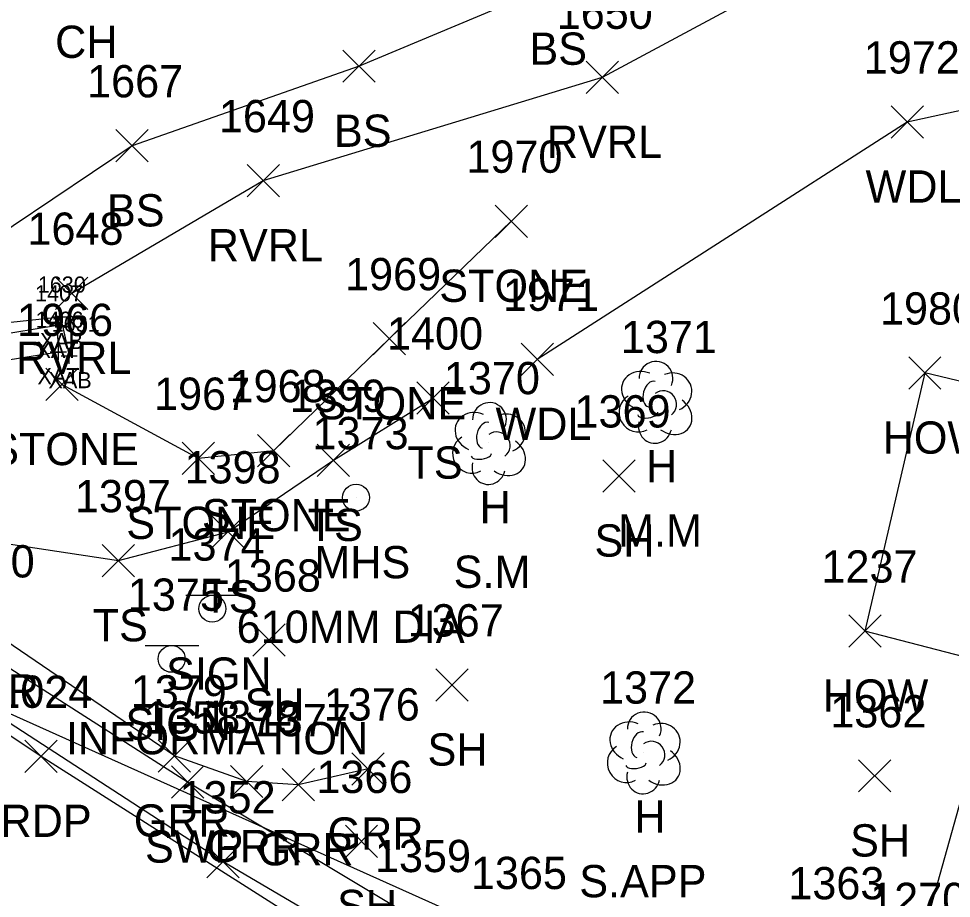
# Model space of a CAD drawing. Extents: x 1616726 to 1619875, y 273782 to 276557.
# Drawn here: x 1617087.2 to 1617145, y 276211.4 to 276265.9 of the extents above; entities that cross this region are included whole.
import ezdxf

# ---------------------------------------------------------------- set-up
doc = ezdxf.new("R2010")
doc.units = 0
for name, color, linetype in [('B_A', 7, 'Continuous'), ('B_I', 7, 'Continuous'), ('B_TIC', 7, 'Continuous'), ('BSUBM', 7, 'Continuous'), ('DCP', 7, 'Continuous'), ('L_A', 7, 'Continuous'), ('L_C', 7, 'Continuous'), ('L_I', 7, 'Continuous'), ('L_TIC', 7, 'Continuous'), ('LASF', 7, 'Continuous'), ('LAWA', 7, 'Continuous'), ('LAWE', 7, 'Continuous'), ('LBC', 7, 'Continuous'), ('LELB', 7, 'Continuous'), ('LTD', 7, 'Continuous'), ('P_A', 7, 'Continuous'), ('P_I', 7, 'Continuous'), ('P_TIC', 7, 'Continuous'), ('PET', 7, 'Continuous'), ('R_A', 7, 'Continuous'), ('R_I', 7, 'Continuous'), ('R_TIC', 7, 'Continuous'), ('RDP', 7, 'Continuous'), ('RGR', 7, 'Continuous'), ('RSW', 7, 'Continuous'), ('S_A', 7, 'Continuous'), ('S_C', 7, 'Continuous'), ('S_I', 7, 'Continuous'), ('SSGN', 7, 'Continuous'), ('U_A', 7, 'Continuous'), ('U_C', 7, 'Continuous'), ('U_I', 7, 'Continuous'), ('USMH', 7, 'Continuous')]:
    doc.layers.add(name, color=color, linetype=linetype)

msp = doc.modelspace()

# ---------------------------------------------------------------- linework, layer by layer
at = {"layer": 'B_TIC'}
for p, q in [((1617089.817, 276247.416), (1617089.893, 276247.416)), ((1617089.624, 276246.874), (1617089.699, 276246.874)), ((1617089.68, 276245.238), (1617089.755, 276245.238)), ((1617090.348, 276244.994), (1617090.423, 276244.994))]:
    msp.add_line(p, q, dxfattribs=at)
for points in [[(1617089.814, 276246.916), (1617089.814, 276247.916)], [(1617089.314, 276247.416), (1617090.314, 276247.416)], [(1617089.62, 276246.374), (1617089.62, 276247.374)], [(1617089.12, 276246.874), (1617090.12, 276246.874)], [(1617089.176, 276245.238), (1617090.176, 276245.238)], [(1617089.676, 276244.738), (1617089.676, 276245.738)], [(1617090.344, 276244.494), (1617090.344, 276245.494)], [(1617089.844, 276244.994), (1617090.844, 276244.994)]]:
    msp.add_lwpolyline(points, dxfattribs=at)
at = {"layer": 'BSUBM'}
for points in [[(1617010.577, 276214.426), (1617009.604, 276215.712), (1617012.165, 276218.528), (1617020.162, 276225.998), (1617024.806, 276230.09), (1617027.157, 276232.146), (1617038.443, 276235.694), (1617050.909, 276239.585), (1617068.456, 276245.114), (1617089.814, 276247.416), (1617090.344, 276244.994)], [(1617069.472, 276243.57), (1617067.092, 276242.73), (1617068.432, 276241.721), (1617069.867, 276242.108), (1617089.676, 276245.238), (1617089.62, 276246.874)], [(1617089.62, 276246.874), (1617069.472, 276243.57)]]:
    msp.add_lwpolyline(points, dxfattribs=at)
at = {"layer": 'DCP'}
msp.add_lwpolyline([(1617248.526, 276150.098), (1617074.525, 276228.268)], dxfattribs=at)
at = {"layer": 'L_TIC'}
for points in [[(1617107.303, 276261.949), (1617109.303, 276263.949)], [(1617109.303, 276261.949), (1617107.303, 276263.949)], [(1617122.367, 276261.261), (1617124.367, 276263.261)], [(1617124.367, 276261.261), (1617122.367, 276263.261)], [(1617141.251, 276258.493), (1617143.251, 276260.493)], [(1617143.251, 276258.493), (1617141.251, 276260.493)], [(1617093.244, 276257.017), (1617095.244, 276259.017)], [(1617095.244, 276257.017), (1617093.244, 276259.017)], [(1617101.367, 276254.855), (1617103.367, 276256.855)], [(1617103.367, 276254.855), (1617101.367, 276256.855)], [(1617116.725, 276252.342), (1617118.725, 276254.342)], [(1617118.725, 276252.342), (1617116.725, 276254.342)], [(1617089.502, 276247.878), (1617091.502, 276249.878)], [(1617091.502, 276247.878), (1617089.502, 276249.878)], [(1617109.18, 276245.064), (1617111.18, 276247.064)], [(1617111.18, 276245.064), (1617109.18, 276247.064)], [(1617118.334, 276243.786), (1617120.334, 276245.786)], [(1617120.334, 276243.786), (1617118.334, 276245.786)], [(1617142.341, 276242.936), (1617144.341, 276244.936)], [(1617144.341, 276242.936), (1617142.341, 276244.936)], [(1617088.91, 276242.226), (1617090.91, 276244.226)], [(1617090.91, 276242.226), (1617088.91, 276244.226)], [(1617111.886, 276241.385), (1617113.886, 276243.385)], [(1617113.886, 276241.385), (1617111.886, 276243.385)], [(1617102.02, 276238.126), (1617104.02, 276240.126)], [(1617104.02, 276238.126), (1617102.02, 276240.126)], [(1617097.342, 276237.652), (1617099.342, 276239.652)], [(1617099.342, 276237.652), (1617097.342, 276239.652)], [(1617105.708, 276237.525), (1617107.708, 276239.525)], [(1617107.708, 276237.525), (1617105.708, 276239.525)], [(1617123.392, 276236.558), (1617125.392, 276238.558)], [(1617125.392, 276236.558), (1617123.392, 276238.558)], [(1617099.185, 276233.092), (1617101.185, 276235.092)], [(1617101.185, 276233.092), (1617099.185, 276235.092)], [(1617092.393, 276231.307), (1617094.393, 276233.307)], [(1617094.393, 276231.307), (1617092.393, 276233.307)], [(1617138.631, 276226.947), (1617140.631, 276228.947)], [(1617140.631, 276226.947), (1617138.631, 276228.947)], [(1617101.724, 276226.387), (1617103.724, 276228.387)], [(1617103.724, 276226.387), (1617101.724, 276228.387)], [(1617113.051, 276223.607), (1617115.051, 276225.607)], [(1617115.051, 276223.607), (1617113.051, 276225.607)], [(1617139.224, 276217.972), (1617141.224, 276219.972)], [(1617141.224, 276217.972), (1617139.224, 276219.972)], [(1617107.452, 276213.908), (1617109.452, 276215.908)], [(1617109.452, 276213.908), (1617107.452, 276215.908)]]:
    msp.add_lwpolyline(points, dxfattribs=at)
at = {"layer": 'LASF'}
msp.add_lwpolyline([(1617089.91, 276243.226), (1617098.342, 276238.652), (1617103.02, 276239.126), (1617110.18, 276246.064), (1617117.725, 276253.342)], dxfattribs=at)
at = {"layer": 'LAWA'}
msp.add_lwpolyline([(1617119.334, 276244.786), (1617142.251, 276259.493), (1617164.142, 276264.272), (1617183.103, 276270.097), (1617194.136, 276272.184)], dxfattribs=at)
at = {"layer": 'LAWE'}
msp.add_lwpolyline([(1617090.502, 276248.878), (1617102.367, 276255.855), (1617123.367, 276262.261), (1617141.244, 276271.864), (1617161.153, 276280.417), (1617181.534, 276284.745)], dxfattribs=at)
at = {"layer": 'LBC'}
for points in [[(1617202.986, 276236.707), (1617169.05, 276244.707), (1617152.443, 276247.898), (1617150.919, 276242.13), (1617143.341, 276243.936)], [(1617143.341, 276243.936), (1617139.631, 276227.947)], [(1617255.861, 276201.85), (1617245.993, 276203.869), (1617245.387, 276204.035), (1617236.024, 276205.957), (1617235.421, 276203.64), (1617213.935, 276208.22), (1617213.334, 276206.295), (1617177.812, 276214.354), (1617179.361, 276218.267), (1617161.118, 276222.362), (1617159.601, 276222.749), (1617139.631, 276227.947)]]:
    msp.add_lwpolyline(points, dxfattribs=at)
at = {"layer": 'LELB'}
for points in [[(1617180.325, 276288.326), (1617161.431, 276281.848), (1617137.104, 276278.445), (1617120.409, 276268.034), (1617108.303, 276262.949), (1617094.244, 276258.017), (1617079.483, 276248.101), (1617068.225, 276247.781), (1617049.151, 276245.503), (1617035.056, 276240.813), (1617026.009, 276236.235), (1617014.974, 276241.9), (1616972.474, 276247.818), (1616960.605, 276245.765), (1616944.032, 276250.468), (1616920.652, 276257.271), (1616898.689, 276263.021), (1616845.503, 276278.094), (1616816.834, 276290.556), (1616792.378, 276296.226)], [(1617074.01, 276240.881), (1617083.704, 276233.783), (1617093.393, 276232.307), (1617100.185, 276234.092), (1617106.708, 276238.525), (1617112.886, 276242.385)]]:
    msp.add_lwpolyline(points, dxfattribs=at)
at = {"layer": 'LTD'}
for p, q in [((1617126.64, 276242.168), (1617126.64, 276242.168)), ((1617126.64, 276242.168), (1617126.64, 276242.168)), ((1617116.332, 276239.62), (1617116.332, 276239.62)), ((1617116.332, 276239.62), (1617116.332, 276239.62)), ((1617125.915, 276220.448), (1617125.915, 276220.448)), ((1617125.915, 276220.448), (1617125.915, 276220.448))]:
    msp.add_line(p, q, dxfattribs=at)
for centre in [(1617126.687, 276243.602), (1617116.379, 276241.054), (1617125.962, 276221.882)]:
    msp.add_arc(centre, 1.047, 335.52715, 180.95627, dxfattribs=at)
for centre, major_axis, ratio, start_param, end_param in [((1617125.848, 276242.835), (1.21, -0.512), 0.895232, 1.570796, 4.712389), ((1617127.681, 276242.752), (-1.141, -0.483), 0.949671, 1.570796, 4.712389), ((1617126.431, 276242.626), (-0.208, -0.792), 0.645439, 3.141593, 6.283185), ((1617127.14, 276242.002), (-0.5, 0.667), 0.989748, 3.141593, 6.283185), ((1617125.557, 276241.46), (0.584, -1.042), 0.959034, 3.141593, 6.283185), ((1617127.64, 276241.335), (-1.09, 0.792), 0.841452, 1.570796, 4.712389), ((1617115.54, 276240.287), (1.21, -0.512), 0.895232, 1.570796, 4.712389), ((1617117.374, 276240.203), (-1.141, -0.483), 0.949671, 1.570796, 4.712389), ((1617126.182, 276241.418), (-0.625, -0.083), 0.423636, 0, 3.141593), ((1617116.124, 276240.078), (-0.208, -0.792), 0.645439, 3.141593, 6.283185), ((1617126.64, 276240.668), (0.265, 1.061), 0.942809, 1.570796, 4.712389), ((1617116.832, 276239.453), (-0.5, 0.667), 0.989748, 3.141593, 6.283185), ((1617115.249, 276238.911), (0.584, -1.042), 0.959034, 3.141593, 6.283185), ((1617117.332, 276238.787), (-1.09, 0.792), 0.841452, 1.570796, 4.712389), ((1617115.874, 276238.87), (-0.625, -0.083), 0.423636, 0, 3.141593), ((1617116.332, 276238.12), (0.265, 1.061), 0.942809, 1.570796, 4.712389), ((1617125.124, 276221.114), (1.21, -0.512), 0.895232, 1.570796, 4.712389), ((1617126.957, 276221.031), (-1.141, -0.483), 0.949671, 1.570796, 4.712389), ((1617125.707, 276220.906), (-0.208, -0.792), 0.645439, 3.141593, 6.283185), ((1617126.415, 276220.281), (-0.5, 0.667), 0.989748, 3.141593, 6.283185), ((1617124.832, 276219.739), (0.584, -1.042), 0.959034, 3.141593, 6.283185), ((1617126.916, 276219.615), (-1.09, 0.792), 0.841452, 1.570796, 4.712389), ((1617125.457, 276219.698), (-0.625, -0.083), 0.423636, 0, 3.141593), ((1617125.916, 276218.948), (0.265, 1.061), 0.942809, 1.570796, 4.712389)]:
    msp.add_ellipse(centre, major_axis=major_axis, ratio=ratio, start_param=start_param, end_param=end_param, dxfattribs=at)
at = {"layer": 'P_TIC'}
for points in [[(1617087.603, 276219.185), (1617089.603, 276221.185)], [(1617089.603, 276219.185), (1617087.603, 276221.185)]]:
    msp.add_lwpolyline(points, dxfattribs=at)
at = {"layer": 'PET'}
msp.add_lwpolyline([(1616989.426, 276201.185), (1617018.474, 276198.311), (1617030.262, 276200.676), (1617036.67, 276206.238), (1617039.512, 276213.461), (1617039.812, 276219.435), (1617036.606, 276227.106), (1617032.436, 276230.391), (1617046.645, 276234.316), (1617061.092, 276238.884), (1617067.899, 276234.233), (1617072.399, 276230.992), (1617088.603, 276220.185), (1617112.483, 276205), (1617131.155, 276194.642), (1617156.357, 276182.31), (1617186.295, 276169.867), (1617215.497, 276159.966), (1617247.442, 276151.441), (1617259.727, 276148.347), (1617264.103, 276152.292), (1617286.332, 276147.086), (1617304.444, 276145.412), (1617352.203, 276136.042)], dxfattribs=at)
at = {"layer": 'R_TIC'}
for points in [[(1617095.861, 276219.205), (1617097.861, 276221.205)], [(1617097.861, 276219.205), (1617095.861, 276221.205)], [(1617107.858, 276218.398), (1617109.858, 276220.398)], [(1617109.858, 276218.398), (1617107.858, 276220.398)], [(1617096.682, 276217.594), (1617098.682, 276219.594)], [(1617098.682, 276217.594), (1617096.682, 276219.594)], [(1617100.347, 276217.621), (1617102.347, 276219.621)], [(1617102.347, 276217.621), (1617100.347, 276219.621)], [(1617103.531, 276217.425), (1617105.531, 276219.425)], [(1617105.531, 276217.425), (1617103.531, 276219.425)], [(1617098.874, 276212.643), (1617100.874, 276214.643)], [(1617100.874, 276212.643), (1617098.874, 276214.643)]]:
    msp.add_lwpolyline(points, dxfattribs=at)
at = {"layer": 'RDP'}
msp.add_lwpolyline([(1617138.754, 276192.085), (1617140.732, 276198.951), (1617142.731, 276207.347), (1617147.723, 276225.136)], dxfattribs=at)
at = {"layer": 'RGR'}
msp.add_lwpolyline([(1617108.858, 276219.398), (1617104.531, 276218.425), (1617101.347, 276218.621), (1617096.861, 276220.205), (1617085.04, 276228.266), (1617070.688, 276238.224), (1617068.011, 276240.729)], dxfattribs=at)
at = {"layer": 'RSW'}
msp.add_lwpolyline([(1617138.329, 276192.204), (1617118.17, 276202.873), (1617099.874, 276213.643), (1617083.833, 276224.055), (1617072.719, 276231.608), (1617068.606, 276234.582), (1617070.344, 276236.957), (1617080.578, 276229.538), (1617097.682, 276218.594), (1617111.983, 276210.006), (1617126.556, 276201.947), (1617139.378, 276195.776)], dxfattribs=at)
at = {"layer": 'SSGN'}
for p, q in [((1617097.563, 276230.162), (1617100.896, 276230.162)), ((1617099.209, 276229.328), (1617099.209, 276229.328)), ((1617095.045, 276227.054), (1617098.378, 276227.054)), ((1617096.692, 276226.22), (1617096.692, 276226.22))]:
    msp.add_line(p, q, dxfattribs=at)
for centre in [(1617099.209, 276229.328), (1617096.692, 276226.22)]:
    msp.add_circle(centre, 0.833, dxfattribs=at)
at = {"layer": 'USMH'}
for p, q in [((1617108.111, 276236.214), (1617108.111, 276236.214)), ((1617108.944, 276236.214), (1617108.944, 276236.214))]:
    msp.add_line(p, q, dxfattribs=at)
msp.add_circle((1617108.111, 276236.214), 0.833, dxfattribs=at)

# ---------------------------------------------------------------- texts
at = {"layer": 'B_A'}
for s, p in [('XAB', (1617088.534, 276245.416)), ('XAT', (1617088.325, 276244.874)), ('XAT', (1617088.381, 276243.238)), ('XAB', (1617089.065, 276242.994))]:
    msp.add_text(s, height=1, dxfattribs=at).set_placement(p)
at = {"layer": 'B_I'}
for s, p in [('1630', (1617088.401, 276248.916)), ('1407', (1617088.235, 276248.374)), ('1406', (1617088.263, 276246.738)), ('1631', (1617089.258, 276246.494))]:
    msp.add_text(s, height=1, dxfattribs=at).set_placement(p)
at = {"layer": 'L_A'}
for s, p in [('CH', (1617089.475, 276263.461)), ('BS', (1617118.85, 276263.034)), ('BS', (1617106.744, 276257.949)), ('RVRL', (1617119.934, 276257.261)), ('WDL', (1617139.668, 276254.493)), ('BS', (1617092.685, 276253.017)), ('RVRL', (1617098.934, 276250.855)), ('STONE', (1617113.268, 276248.342)), ('RVRL', (1617087.069, 276243.878)), ('STONE', (1617105.723, 276241.064)), ('WDL', (1617116.751, 276239.786)), ('HOW', (1617140.727, 276238.936)), ('STONE', (1617085.453, 276238.226)), ('TS', (1617111.296, 276237.385)), ('H', (1617126.073, 276237.168)), ('H', (1617115.765, 276234.62)), ('STONE', (1617098.564, 276234.126)), ('STONE', (1617093.886, 276233.652)), ('TS', (1617105.118, 276233.525)), ('SH', (1617122.88, 276232.558)), ('TS', (1617098.594, 276229.092)), ('TS', (1617091.803, 276227.307)), ('HOW', (1617137.017, 276222.947)), ('SH', (1617101.212, 276222.387)), ('SH', (1617112.539, 276219.607)), ('H', (1617125.349, 276215.448)), ('SH', (1617138.712, 276213.972)), ('SH', (1617106.94, 276209.908))]:
    msp.add_text(s, height=2, dxfattribs=at).set_placement(p)
at = {"layer": 'L_C'}
for s, p in [('M.M', (1617124.341, 276233.168)), ('S.M', (1617114.159, 276230.62)), ('S.APP', (1617121.939, 276211.448))]:
    msp.add_text(s, height=2, dxfattribs=at).set_placement(p)
at = {"layer": 'L_I'}
for s, p in [('1650', (1617120.54, 276265.261)), ('1972', (1617139.558, 276262.493)), ('1667', (1617091.457, 276261.017)), ('1649', (1617099.619, 276258.855)), ('1970', (1617114.945, 276256.342)), ('1648', (1617087.762, 276251.878)), ('1969', (1617107.432, 276249.064)), ('1971', (1617117.208, 276247.786)), ('1980', (1617140.562, 276246.936)), ('1966', (1617087.115, 276246.226)), ('1400', (1617110.028, 276245.385)), ('1371', (1617124.514, 276245.168)), ('1370', (1617113.552, 276242.62)), ('1968', (1617100.28, 276242.126)), ('1967', (1617095.602, 276241.652)), ('1399', (1617104.008, 276241.525)), ('1369', (1617121.644, 276240.558)), ('1398', (1617097.492, 276237.092)), ('1397', (1617090.701, 276235.307)), ('1237', (1617136.938, 276230.947)), ('1368', (1617099.984, 276230.387)), ('1367', (1617111.311, 276227.607)), ('1372', (1617123.223, 276223.448)), ('1362', (1617137.484, 276221.972)), ('1366', (1617105.656, 276217.908)), ('1365', (1617115.225, 276211.956)), ('1363', (1617134.884, 276211.321))]:
    msp.add_text(s, height=2, dxfattribs=at).set_placement(p)
at = {"layer": 'P_A'}
msp.add_text('RDP', height=2, dxfattribs=at).set_placement((1617086.091, 276215.185))
at = {"layer": 'P_I'}
msp.add_text('1024', height=2, dxfattribs=at).set_placement((1617085.832, 276223.185))
at = {"layer": 'R_A'}
for s, p in [('GRR', (1617082.528, 276223.266)), ('GRR', (1617094.349, 276215.205)), ('GRR', (1617106.347, 276214.398)), ('SWP', (1617095.045, 276213.594)), ('GRR', (1617098.835, 276213.621)), ('GRR', (1617102.019, 276213.425))]:
    msp.add_text(s, height=2, dxfattribs=at).set_placement(p)
at = {"layer": 'R_I'}
for s, p in [('1380', (1617082.26, 276231.266)), ('1379', (1617094.16, 276223.205)), ('1376', (1617106.11, 276222.398)), ('1358', (1617094.989, 276221.594)), ('1378', (1617098.654, 276221.621)), ('1377', (1617101.838, 276221.425)), ('1352', (1617097.181, 276216.643)), ('1359', (1617109.283, 276213.006)), ('1270', (1617139.951, 276210.347))]:
    msp.add_text(s, height=2, dxfattribs=at).set_placement(p)
at = {"layer": 'S_A'}
for p in [(1617096.347, 276224.308), (1617093.83, 276221.2)]:
    msp.add_text('SIGN', height=2, dxfattribs=at).set_placement(p)
at = {"layer": 'S_C'}
msp.add_text('INFORMATION', height=2, dxfattribs=at).set_placement((1617090.143, 276220.308))
at = {"layer": 'S_I'}
for s, p in [('1374', (1617096.497, 276232.308)), ('1375', (1617093.979, 276229.2))]:
    msp.add_text(s, height=2, dxfattribs=at).set_placement(p)
at = {"layer": 'U_A'}
msp.add_text('MHS', height=2, dxfattribs=at).set_placement((1617105.528, 276231.214))
at = {"layer": 'U_C'}
msp.add_text('610MM DIA', height=2, dxfattribs=at).set_placement((1617100.717, 276227.214))
at = {"layer": 'U_I'}
msp.add_text('1373', height=2, dxfattribs=at).set_placement((1617105.418, 276239.214))

doc.saveas('drawing.dxf')
